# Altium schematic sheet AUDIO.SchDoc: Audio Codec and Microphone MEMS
size A4; Date: 01-DEC-2013; Author: A.B; CompanyName: STMicroelectronics; Organization: Microcontrollers Division; Address1: 12, Rue Jules HOROWITZ; Address2: 38019 Grenoble; Address3: FRANCE; DocumentNumber: MB1184; Revision: C-01; SheetNumber: 8; SheetTotal: 10; Project: STM32L476G-DISCO
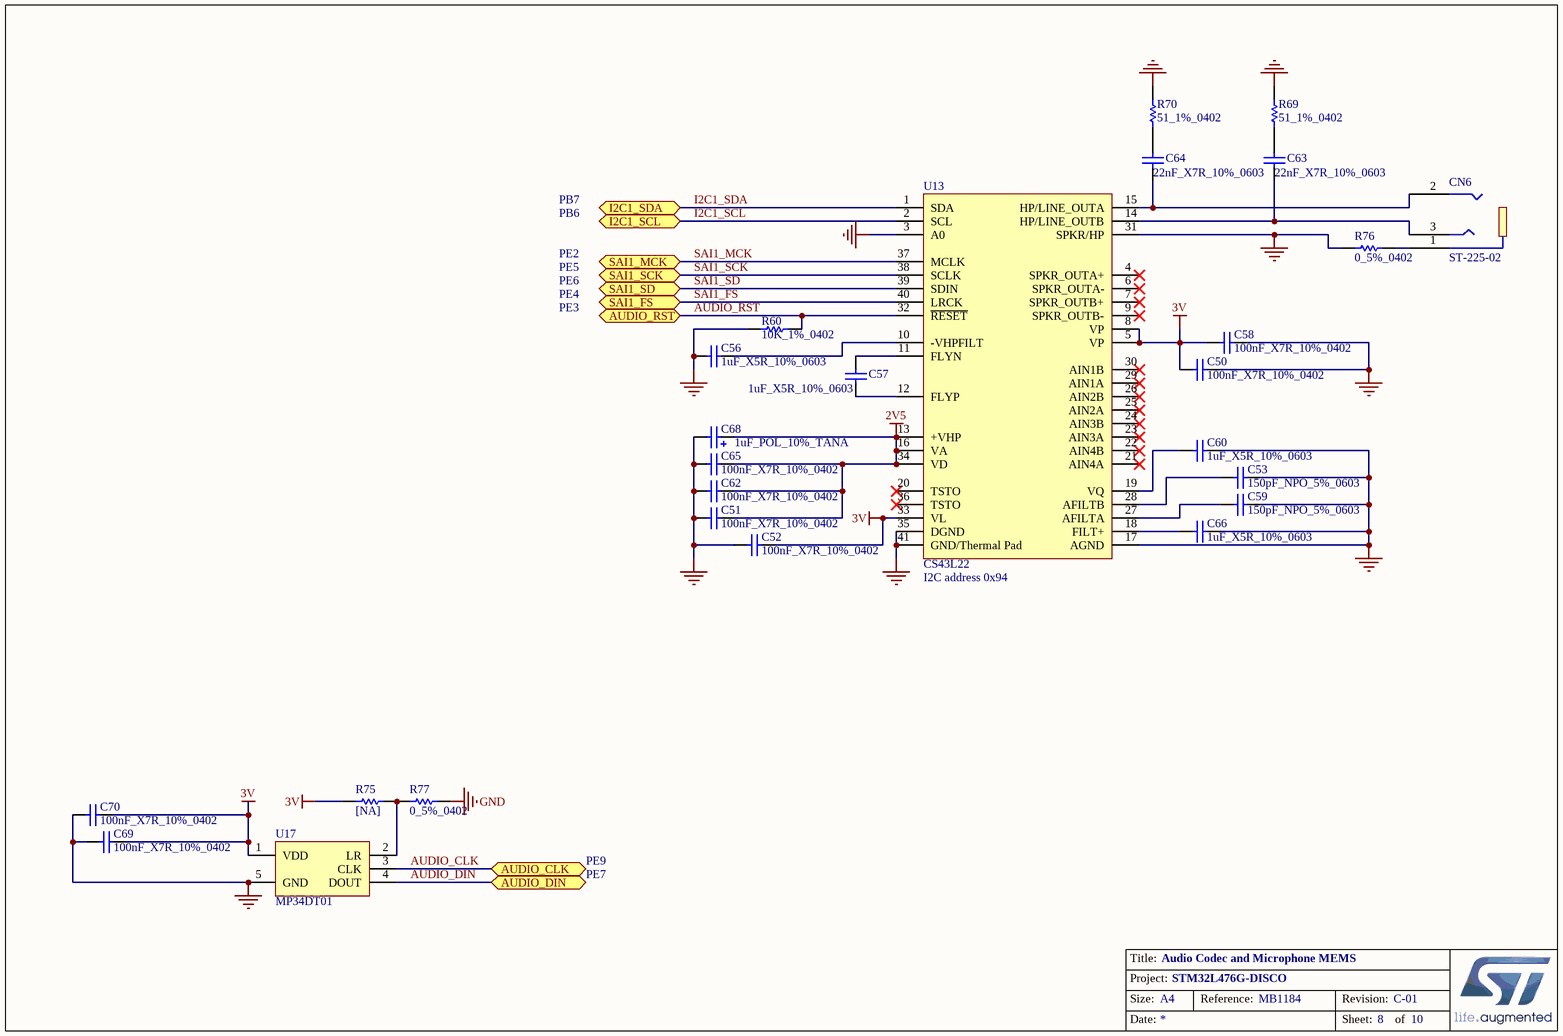
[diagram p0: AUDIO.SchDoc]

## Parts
C50  100nF_X7R_10%_0402  [0402C]
C51  100nF_X7R_10%_0402  [0402C]
C52  100nF_X7R_10%_0402  [0402C]
C53  150pF_NPO_5%_0603  [0603C]
C56  1uF_X5R_10%_0603  [0603C]
C57  1uF_X5R_10%_0603  [0603C]
C58  100nF_X7R_10%_0402  [0402C]
C59  150pF_NPO_5%_0603  [0603C]
C60  1uF_X5R_10%_0603  [0603C]
C62  100nF_X7R_10%_0402  [0402C]
C63  22nF_X7R_10%_0603  [0603C]
C64  22nF_X7R_10%_0603  [0603C]
C65  100nF_X7R_10%_0402  [0402C]
C66  1uF_X5R_10%_0603  [0603C]
C68  1uF_POL_10%_TANA  [TAN-A]
C69  100nF_X7R_10%_0402  [0402C]
C70  100nF_X7R_10%_0402  [0402C]
CN6  ST-225-02  [Jack-ST-225]
R60  10K_1%_0402  [0402R]
R69  51_1%_0402  [0402R]
R70  51_1%_0402  [0402R]
R75  [NA]  [0402R]
R76  0_5%_0402  [0402R]
R77  0_5%_0402  [0402R]
U13  CS43L22  [QFN40_6x6]
U17  MP34DT01  [HCLGA4_3X4]

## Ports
AUDIO_CLK, AUDIO_DIN, AUDIO_RST, I2C1_SCL, I2C1_SDA, SAI1_FS, SAI1_MCK, SAI1_SCK, SAI1_SD

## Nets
2V5: C51.2 C62.2 C65.2 C68.1 U13.13(+VHP) U13.16(VA) U13.34(VD)
3V: C50.1 C52.2 C58.1 C69.2 C70.2 R75.2 U13.5(VP) U13.8(VP) U13.33(VL) U17.1(VDD)
GND: C50.2 C51.1 C52.1 C53.2 C56.1 C58.2 C59.2 C60.2 C62.1 C65.1 C66.2 C68.2 C69.1 C70.1 R60.1 R69.2 R70.2 R76.1 R77.1 U13.3(A0) U13.17(AGND) U13.31(SPKR/HP) U13.35(DGND) U13.41(GND/Thermal_Pad) U17.5(GND)
AUDIO_CLK: U17.3(CLK) ; port AUDIO_CLK
AUDIO_DIN: U17.4(DOUT) ; port AUDIO_DIN
AUDIO_RST: R60.2 U13.32(~{RESET}) ; port AUDIO_RST
I2C1_SCL: U13.2(SCL) ; port I2C1_SCL
I2C1_SDA: U13.1(SDA) ; port I2C1_SDA
SAI1_FS: U13.40(LRCK) ; port SAI1_FS
SAI1_MCK: U13.37(MCLK) ; port SAI1_MCK
SAI1_SCK: U13.38(SCLK) ; port SAI1_SCK
SAI1_SD: U13.39(SDIN) ; port SAI1_SD
NetC53_1: C53.1 U13.28(AFILTB)
NetC56_2: C56.2 U13.10(-VHPFILT)
NetC57_1: C57.1 U13.12(FLYP)
NetC57_2: C57.2 U13.11(FLYN)
NetC59_1: C59.1 U13.27(AFILTA)
NetC60_1: C60.1 U13.19(VQ)
NetC63_1: C63.1 CN6.3 U13.14(HP/LINE_OUTB)
NetC63_2: C63.2 R69.1
NetC64_1: C64.1 CN6.2 U13.15(HP/LINE_OUTA)
NetC64_2: C64.2 R70.1
NetC66_1: C66.1 U13.18(FILT+)
NetCN6_1: CN6.1 R76.2
NetR75_1: R75.1 R77.2 U17.2(LR)

Not connected (* = marked no-connect by the designer): U13 4(SPKR_OUTA+)* 6(SPKR_OUTA-)* 7(SPKR_OUTB+)* 9(SPKR_OUTB-)* 20(TSTO)* 21(AIN4A)* 22(AIN4B)* 23(AIN3A)* 24(AIN3B)* 25(AIN2A)* 26(AIN2B)* 29(AIN1A)* 30(AIN1B)* 36(TSTO)*

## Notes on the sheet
- PB7
- PB6
- PE3
- PE2
- PE4
- PE5
- PE6
- (near U13) I2C address 0x94
- PE9
- PE7

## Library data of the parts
C50-C52 C58 C62 C65 C69 C70 = Cap_100nF_X7R_10%_0402: Capacitor,100nF,16V,X7R,10%,0402,YAGEO; Manuf_Part_1: CC0402KRX7R7BB104
C53 C59 = Cap_150pF_NPO_5%_0603: Capacitor,150pF,50V,NPO,5%,0603,YAGEO; Order: CC0603JRNPO9BN151
C56 C57 C60 C66 = Cap_1uF_X5R_10%_0603: Capacitor,1uF,16V,X5R,10%,0603,YAGEO; Manuf_Part_1: CC0603KRX5R7BB105
C63 C64 = Cap_22nF_X7R_10%_0603: Capacitor,22nF,50V,X7R,10%,0603,YAGEO; Manuf_Part_1: CC0603KRX7R9BB223
C68 = Cap_1uF_POL_10%_TANA: Polarized Capacitor,1uF,16V,10%,typeA,AVX; Manuf_Part_1: TAJA105K016R
CN6 = ST-225-02: Connector Jack 3.5mm; Manuf_1: XIEJIA Electronics
R60 = Res_10K_1%_0402: Resistor,10K,0402,1%,YAGEO; Manuf_Part_1: RC0402FR-0710KL
R69 R70 = Res_51_1%_0402: Resistor,51,0402,1%,YAGEO; Manuf_Part_1: RC0402FR-0751RL; Value: 51; Order: 311-51.0LRTR-ND
R75 = Res_NA_0402: Resistor,[NA],0402; Fitted: NO
R76 R77 = Res_0_5%_0402: Resistor,0,0402,5%,YAGEO; Manuf_Part_1: RC0402JR-070RL; Value: 0; Order: 2363467
U13 = CS43L22: Low Power, Stereo DAC w/Headphone & Speaker Amps; Manuf_1: Cirrus; Order: CS43L22-CNZ; ECCN_US/EU: EAR99/NEC
U17 = MP34DT01: MEMS audio sensor, omnidirectional digital microphone; Manuf_1: STM; Manuf_Part_1: MP34DT01TR; Provided: ST; Ref St: 9188008; ECCN_US/EU: EAR99/NEC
